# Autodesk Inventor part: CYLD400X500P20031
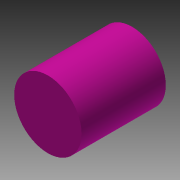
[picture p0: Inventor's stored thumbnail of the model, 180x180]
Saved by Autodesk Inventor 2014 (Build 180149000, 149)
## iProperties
Shininess: 64.0
Length Units: 11272
Angle Units: 11279
Time Units: 11290
Mass Units: 11286
Length Display Precision: 3
Angle Display Precision: 2
Compacted: True
Part Number: CYLD400X500P20031
Document SubType Name: Modeling
Created: 2003-04
Designer: t_enrig
Manufacturer: Standard
Standards Organization: Custom
Density: 1 g/cm^3
Mass: 1.02963 g
Surface Area: 5.67512 cm^2
Volume: 1.02963 cm^3
Material: Generic
Appearance: TranslatedColorStyle
Density: 0.0
Volumn: 0.0
Area: 0.0
PropertySet Name: Model Information
Control State: 0
Master: False
Checked Out: False
Author: t_enrig
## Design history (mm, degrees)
feature "Base1"
body "Solid1"
